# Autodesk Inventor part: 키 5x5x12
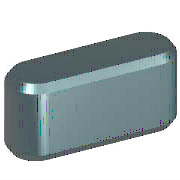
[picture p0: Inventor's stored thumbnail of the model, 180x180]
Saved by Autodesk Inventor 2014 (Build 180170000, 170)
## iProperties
IsCustomPart: 1
Created: 2012-02
Part Number: 키 5x5x12
Material: 강철, 연강
Description: 키 및 해당 키홈
Document SubType Name: Modeling
Standard: KS B 1311
Designer: mduedu
Standards Organization: KS
Language: ko-KR
Size Designation: 5 x 5 x 12
Categories: <MemberInstance><Categories><Category DisplayName="샤프트 부품" InternalName="7f7aeb1f-a693-4053-b835-cee3144e0d98" Mnemonic="SHFT"><Category DisplayName="키" Interna
Density: 1 g/cm^3
Appearance: 노란색
Author: mduedu
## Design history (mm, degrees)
workplane "Work Plane1"
workplane "Work Plane2"
sketch "스케치1"
  geometry: L1 (2.5, 2.5)-(9.5, 2.5); L2 (9.5, -2.5)-(2.5, -2.5); L3 (0, 9.4)-(0, -7.4) reference; L4 (-5, 0)-(30, 0) reference; L5 (12, 0)-(12, 7); A1 r 2.5 centre (2.5, 0) between (2.5, 2.5) and (2.5, -2.5); A2 r 2.5 centre (9.5, 0) between (9.5, -2.5) and (9.5, 2.5)
  constraints: 6 end point, 5 point on circle, 4 tangent, 3 point on line, 2 centre point, 1 horizontal, 1 parallel, 1 perpendicular
  dimensions: "d0" = 2.5 radius of A1 (= 0.5 x PB); "d13" = 2.5 radius of A2 (= 0.5 x PB); "d14" = 12 distance between parallel lines of L5 L3 (= NLG)
extrude "본체1" new body sketch "스케치1" taper "d3" = 0 deg; stored distance "d4" = 10
workplane "Work Plane3"
body "Solid1"
chamfer "모따기1" distance "d8" = 0.4 (= PHH); stored, may be unused: second distance "d9" = 0.4 (= PHH), angle "d15" = 45 deg
other parameters: "d1" = -3 (= -PNT), "d2" = 2 (= PH - PNT), "NLG" = 12 [user parameter; used in 3 equation terms], "PB" = 5 [user parameter; used in 2 equation terms], "PNT" = 3 [user parameter; used in 2 equation terms], "PH" = 5 [user parameter; used in 1 equation term], "PHH" = 0.4 [user parameter; used in 2 equation terms], "d10" = 0, "d16" = 0, "d17" = 0, "d18" = 0, "WDMIN" = 12 [user parameter], "PLB2" = 12 (= NLG) [user parameter], "WDMAX" = 17 [user parameter], "PLB1" = 12 (= NLG) [user parameter], "RR" = 0.16 [user parameter], "PUEB" = 2.3 [user parameter]
